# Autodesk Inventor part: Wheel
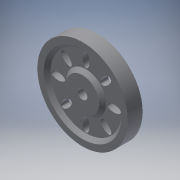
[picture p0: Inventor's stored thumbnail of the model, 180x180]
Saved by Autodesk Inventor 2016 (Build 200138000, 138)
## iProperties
Created: 2016-07
Part Number: Wheel
Material: Generic
Document SubType Name: Modeling
Designer: jose
Density: 1 g/cm^3
Appearance: Default
Author: jose
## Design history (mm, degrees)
sketch "Sketch1"
  geometry: C1 r 35.115 at (0, 0); 1 further point
  constraints: 1 centre point, 1 coincident
  dimensions: "d0" = 70.231 diameter of C1
extrude "Extrusion1" new body sketch "Sketch1" distance "d1" = 11.176; taper "d2" = 0 deg
sketch "Sketch2"
  geometry: C1 r 30.607 at (0, 0); 1 further point
  constraints: 1 centre point, 1 coincident
  dimensions: "d21" = 61.214 diameter of C1
extrude "Extrusion2" cut sketch "Sketch2" distance "d3" = 1.3462; taper "d4" = 0 deg
sketch "Sketch6"
  geometry: C1 r 27.191 at (0, 0); 1 further point
  constraints: 1 centre point, 1 coincident
  dimensions: "d22" = 54.3814 diameter of C1
extrude "Extrusion6" cut sketch "Sketch6" distance "d23" = 3.8862; taper "d24" = 0 deg
sketch "Sketch7"
  geometry: C1 r 30.607 at (0, 0) reference; 1 further point
extrude "Extrusion7" cut sketch "Sketch7" distance "d25" = 1.3462; taper "d26" = 0 deg
sketch "Sketch8"
  geometry: C1 r 28.346 at (0, 0); 1 further point
  constraints: 1 centre point, 1 coincident
  dimensions: "d27" = 56.6928 diameter of C1
extrude "Extrusion8" cut sketch "Sketch8" distance "d28" = 3.7338; taper "d29" = 0 deg
sketch "Sketch9"
  geometry: C1 r 5.499 at (0, 0); 1 further point
  constraints: 1 centre point, 1 coincident
  dimensions: "d30" = 10.9982 diameter of C1
extrude "Extrusion9" join sketch "Sketch9" distance "d31" = 4.1656; taper "d32" = 0 deg
sketch "Sketch10"
  geometry: C1 r 2.667 at (0, 0); 1 further point
  constraints: 1 centre point, 1 coincident
  dimensions: "d33" = 5.334 diameter of C1
extrude "Extrusion10" cut sketch "Sketch10" distance "d34" = 4.9784; taper "d35" = 0 deg
sketch "Sketch12"
  geometry: C1 r 9.843 at (0, 0); 1 further point
  constraints: 1 centre point, 1 coincident
  dimensions: "d39" = 19.685 diameter of C1
extrude "Extrusion12" join sketch "Sketch12" distance "d40" = 1.27; taper "d41" = 0 deg
sketch "Sketch11"
  geometry: C1 r 1.372 at (0, 0); 1 further point
  constraints: 1 centre point, 1 coincident
  dimensions: "d36" = 2.7432 diameter of C1
extrude "Extrusion11" cut sketch "Sketch11" stored distance "d37" = 4.9784; taper "d38" = 0 deg
sketch "Sketch13"
  geometry: C1 r 2.667 at (0, 0) reference; 1 further point
extrude "Extrusion13" cut sketch "Sketch13" distance "d42" = 0.254; taper "d43" = 0 deg
sketch "Sketch14" dims "d44" = 5.6134, "d45" = 3.8481
  geometry: C1 r 35.115 at (0, 0) reference; 2 further points; 1 other entity
  constraints: 2 other
  dimensions: "d46" = 17.78 distance of C1.centre point (0, 17.78)
extrude "Extrusion14" cut sketch "Sketch14" stored distance "d47" = 0; taper "d48" = 0 deg
pattern_circular "Circular Pattern2" dims angle "d50" = 360 deg
sketch "Sketch15"
  geometry: L1 (0, 0)-(26.26, 26.26); L2 (0, 0)-(45.646, 0); L3 (0, 0)-(0, 40.761); C1 r 0.762 at (0, 7.874); C2 r 1.524 at (4.966, 4.966); C3 r 5.499 at (0, 0) reference
  constraints: 6 end point, 2 centre point, 2 point on line, 1 horizontal, 1 tangent, 1 vertical
  dimensions: "d52" = 45 deg angle of L2 L1; "d53" = 1.524 diameter of C1; "d54" = 3.048 diameter of C2; "d56" = 7.874 distance of L1.start C1.centre
extrude "Extrusion15" cut sketch "Sketch15" stored distance "d57" = 0.254; taper "d58" = 0 deg
pattern_circular "Circular Pattern3" dims angle "d60" = 360 deg
body "Solid1"
